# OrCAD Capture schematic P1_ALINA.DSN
size A
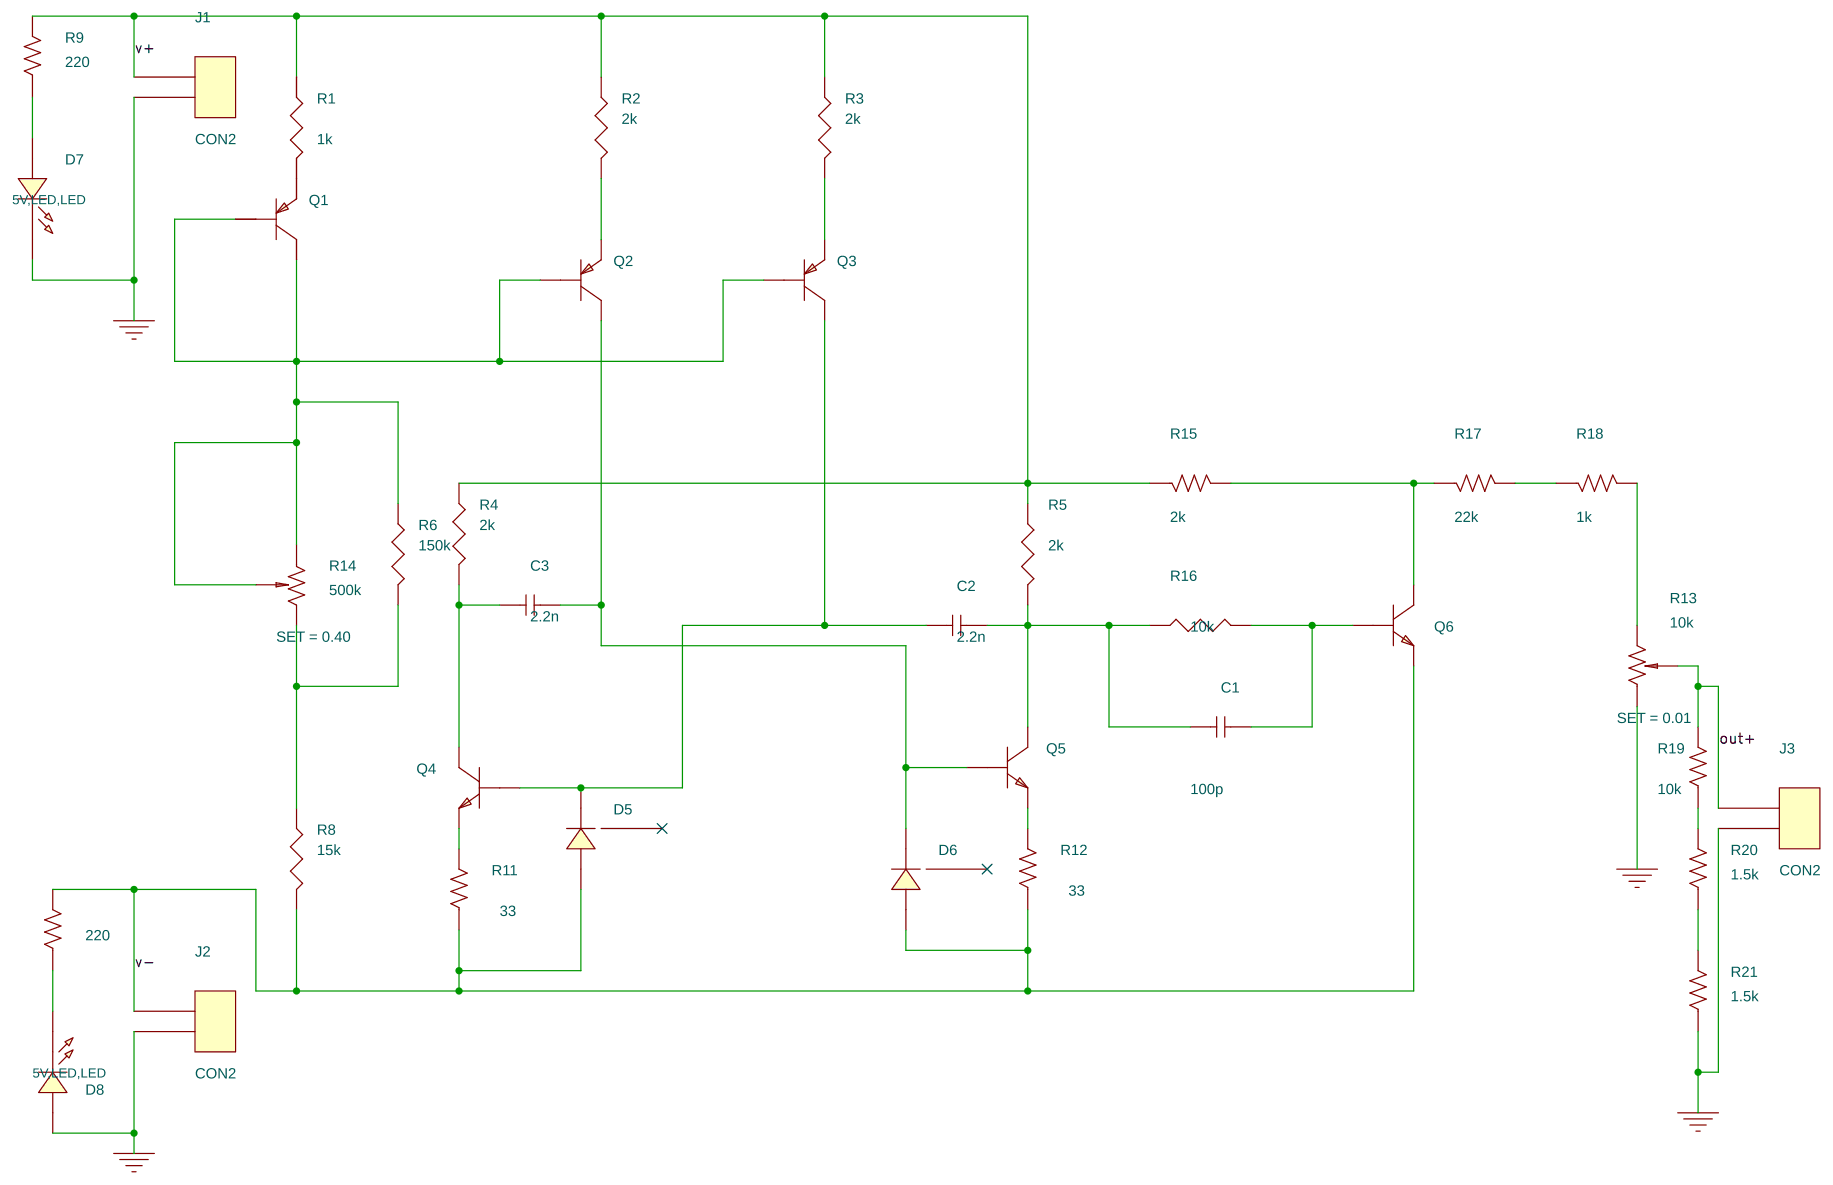
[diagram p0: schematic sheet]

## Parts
C1  100p  [SMC0805]
C2  2.2n  [SMC0805]
C3  2.2n  [SMC0805]
D5  BZX84-C5V6  [TO236AA]
D6  BZX84-C5V6  [TO236AA]
D7  5V,LED,LED  [SMD0805]
D8  5V,LED,LED  [SMD0805]
J1  CON2  [SMR2512]
J2  CON2  [SMR2512]
J3  CON2  [SMR2512]
Q1  QBC856B  [TO236AA]
Q2  QBC856B  [TO236AA]
Q3  QBC856B  [TO236AA]
Q4  QBC846B  [TO236AA]
Q5  QBC846B  [TO236AA]
Q6  QBC846B  [TO236AA]
R1  1k  [SMR0805]
R2  2k  [SMR0805]
R3  2k  [smr0805]
R4  2k  [SMR0805]
R5  2k  [SMR0805]
R6  150k  [SMR0805]
R8  15k  [SMR0805]
R9  220  [SMR0805]
R10  220  [SMR0805]
R11  33  [SMR0805]
R12  33  [SMR0805]
R13  10k  [TS53YL]
R14  500k  [TS53YL]
R15  2k  [SMR0805]
R16  10k  [SMR0805]
R17  22k  [SMR0805]
R18  1k  [SMR0805]
R19  10k  [SMR0805]
R20  1.5k  [SMR0805]
R21  1.5k  [SMR0805]

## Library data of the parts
C1-C3 = C
D5 D6 = BZX84-C5V6_0
D7 D8 = LED_0: AppProp: mN=LED,fV=3,fC=30E-3; BV: 5; IBV: 10e-6; IF: 160E-3; IS: 2.6404e-027; PDM: 114E-3; RS: 2; VR: 5
J1-J3 = CON2
Q1-Q3 = QBC856B_0
Q4-Q6 = QBC846B_0
R1-R6 R8 R16 = R_v2
R9-R12 R15 R17-R21 = R
R13 = POT_0: SET: 0.01
R14 = POT_0: SET: 0.40

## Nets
GND: D7.C D8.A J1.2 J2.2 J3.2 R13.1(CCW) R21.1
out+: J3.1 R13.2(WIPER) R19.2
v+: J1.1 R1.1 R2.1 R3.1 R4.1 R5.1 R9.2 R15.1
v-: D5.1(A) D6.1(A) J2.1 Q6.2(E) R8.2 R10.2 R11.1 R12.1
N00566: Q2.2(E) R2.2
N00570: Q3.2(E) R3.2
N00574: Q1.1(B) Q1.3(C) Q2.1(B) Q3.1(B) R6.1 R14.1(CCW) R14.2(WIPER)
N00648: C3.2 D6.3(C) Q2.3(C) Q5.1(B)
N00689: C3.1 Q4.3(C) R4.2
N00735: C2.1 D5.3(C) Q3.3(C) Q4.1(B)
N00812: C1.1 C2.2 Q5.3(C) R5.2 R16.1
N01285: C1.2 Q6.1(B) R16.2
N02107: R6.2 R8.1 R14.3(CW)
N13335: Q6.3(C) R15.2 R17.1
N15152: R13.3(CW) R18.2
N42140: R19.1 R20.2
N42144: R20.1 R21.2
N48070: Q4.2(E) R11.2
N48898: D7.A R9.1
N51295: Q5.2(E) R12.2
N55134: R17.2 R18.1
N57759: D8.C R10.1
N70419: Q1.2(E) R1.2

Not connected (* = marked no-connect by the designer): D5 2*; D6 2*
